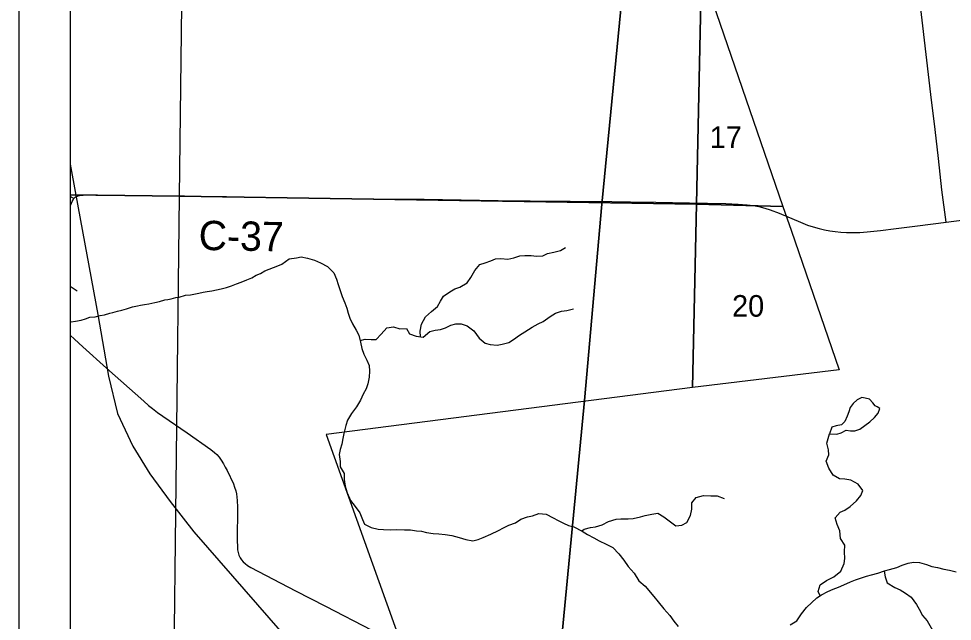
# Model space of a CAD drawing. Extents: x 0 to 34, y -5.4 to 22.
# Drawn here: x 2 to 3.809, y 15.324 to 16.492 of the extents above; entities that cross this region are included whole.
import ezdxf

# ---------------------------------------------------------------- set-up
doc = ezdxf.new("R2010")
doc.units = 0
for name, color, linetype in [('Default', 7, 'Continuous'), ('GM_X_County_Road', 7, 'Continuous'), ('GM_X_County_Road_Text', 7, 'Continuous'), ('GM_X_Minor_Lake', 7, 'Continuous'), ('GM_X_Minor_River', 7, 'Continuous'), ('GM_X_Rail_Line', 7, 'Continuous'), ('GM_X_Section', 7, 'Continuous'), ('GM_X_Section_Text', 7, 'Continuous'), ('GM_X_Township_Road', 7, 'Continuous'), ('SH_Data', 7, 'Continuous')]:
    doc.layers.add(name, color=color, linetype=linetype)

msp = doc.modelspace()

# ---------------------------------------------------------------- linework, layer by layer
at = {"layer": 'Default'}
for points in [[(2.1, 17.1559), (2.1, 16.1508), (2.3117, 16.1481), (2.3239, 17.1531)], [(2.1, 16.1508), (2.1, 15.1447), (2.2999, 15.1427), (2.3117, 16.1481)]]:
    msp.add_lwpolyline(points, close=True, dxfattribs=at)
at = {"layer": 'GM_X_County_Road'}
for points in [[(2.1072, 16.1435), (2.102, 16.1464), (2.1, 16.1475)], [(2.1, 16.1292), (2.1004, 16.13), (2.1023, 16.1343), (2.1039, 16.1377), (2.1054, 16.1407), (2.1072, 16.1435)], [(2.1072, 16.1435), (2.1087, 16.1452), (2.1101, 16.1465), (2.1124, 16.1477), (2.115, 16.1487), (2.1181, 16.1494), (2.1209, 16.1499), (2.1252, 16.1503), (2.1328, 16.1505), (2.1496, 16.1502), (2.1826, 16.1497), (2.275, 16.1487), (2.3214, 16.1484), (2.373, 16.1476), (2.4028, 16.1472), (2.4525, 16.1463), (2.5171, 16.1456), (2.5593, 16.1448), (2.6401, 16.1437), (2.6885, 16.1432), (2.7854, 16.142), (2.9289, 16.1399), (2.991, 16.1392), (3.0687, 16.1385), (3.1495, 16.1376), (3.1624, 16.1373)], [(3.1624, 16.1373), (3.1855, 16.137), (3.2346, 16.1362), (3.2998, 16.1353), (3.37, 16.1336), (3.3942, 16.1326), (3.4115, 16.1313), (3.4231, 16.1298), (3.4341, 16.1278), (3.446, 16.1247), (3.4559, 16.1215), (3.4734, 16.1148), (3.5147, 16.0975), (3.5286, 16.0921), (3.5392, 16.0885), (3.5513, 16.0853), (3.5614, 16.0827), (3.572, 16.0807), (3.5819, 16.0794), (3.5931, 16.0784), (3.6043, 16.0776), (3.6161, 16.0773), (3.6298, 16.0777), (3.6441, 16.0788), (3.6701, 16.0816), (3.7003, 16.0855), (3.7416, 16.0906), (3.7969, 16.0976), (3.9522, 16.1174)], [(2.1, 15.8783), (2.1084, 15.8705), (2.1246, 15.8559), (2.1703, 15.8148), (2.2426, 15.7504), (2.2517, 15.7425), (2.2595, 15.7363), (2.2689, 15.7289), (2.2791, 15.7216), (2.3263, 15.689), (2.3726, 15.6566), (2.3794, 15.6513), (2.3839, 15.6472), (2.3883, 15.6423), (2.3922, 15.6365), (2.3967, 15.6292), (2.4004, 15.6228), (2.4038, 15.6161), (2.416, 15.5903), (2.4184, 15.5838), (2.4206, 15.5766), (2.4219, 15.5709), (2.4228, 15.5644), (2.4234, 15.5581), (2.4239, 15.5451), (2.4235, 15.4789), (2.4237, 15.4692), (2.4242, 15.4624), (2.4251, 15.4573), (2.4268, 15.4519), (2.4293, 15.4468), (2.4319, 15.443), (2.4351, 15.4391), (2.4387, 15.4356), (2.4432, 15.432), (2.4499, 15.4279), (2.5362, 15.383), (2.5943, 15.3533), (2.6843, 15.3064)]]:
    msp.add_lwpolyline(points, dxfattribs=at)
at = {"layer": 'GM_X_Minor_Lake'}
for points in [[(3.6634, 15.7393), (3.6594, 15.7415), (3.6553, 15.7473), (3.6486, 15.7546), (3.6399, 15.7563), (3.6335, 15.7575), (3.6247, 15.7531), (3.6167, 15.746), (3.6112, 15.7385), (3.6085, 15.7302), (3.6053, 15.7215), (3.601, 15.7113), (3.5941, 15.705), (3.5842, 15.7025), (3.5754, 15.7003), (3.5713, 15.6872)], [(3.5713, 15.6872), (3.5851, 15.6865), (3.5934, 15.689), (3.6037, 15.6946), (3.6117, 15.6933), (3.62, 15.6928), (3.6299, 15.6964), (3.6395, 15.7031), (3.6491, 15.7106), (3.6583, 15.7192), (3.6652, 15.7274), (3.6684, 15.7365), (3.6634, 15.7393)]]:
    msp.add_lwpolyline(points, dxfattribs=at)
at = {"layer": 'GM_X_Minor_River'}
for points in [[(2.7783, 15.8754), (2.778, 15.8866), (2.7805, 15.9002), (2.7883, 15.9138), (2.7999, 15.9246), (2.8114, 15.9339), (2.8176, 15.9444), (2.8234, 15.9541), (2.8357, 15.9627), (2.8452, 15.9682), (2.8548, 15.9718), (2.8689, 15.9799), (2.8759, 15.9904), (2.8837, 16.004), (2.8933, 16.0155), (2.9036, 16.0188), (2.9146, 16.0228), (2.9242, 16.0268), (2.9344, 16.027), (2.9476, 16.0256), (2.9594, 16.0288), (2.9708, 16.0324), (2.981, 16.033), (2.9928, 16.0328), (3.0033, 16.0319), (3.0155, 16.0324), (3.025, 16.0368), (3.0372, 16.0397), (3.0501, 16.0425), (3.0596, 16.0484)], [(2.524, 16.0268), (2.5382, 16.0284), (2.5477, 16.0302), (2.5594, 16.0277), (2.5729, 16.0237), (2.585, 16.0185), (2.5985, 16.0119), (2.6108, 15.9995), (2.6158, 15.9869), (2.6191, 15.977), (2.6227, 15.9651), (2.6267, 15.9537), (2.6321, 15.9415), (2.6357, 15.9312), (2.6386, 15.9212), (2.6419, 15.9117), (2.647, 15.9006), (2.654, 15.8884), (2.6591, 15.8788), (2.6623, 15.8651), (2.6647, 15.8525), (2.6691, 15.8414), (2.6746, 15.83), (2.6789, 15.82), (2.6799, 15.8086), (2.6793, 15.7969), (2.6764, 15.7844), (2.6736, 15.7746), (2.6678, 15.7641), (2.6623, 15.7528), (2.6549, 15.7396), (2.6448, 15.7265), (2.6374, 15.7137), (2.6338, 15.7032), (2.6302, 15.6881), (2.6278, 15.6783), (2.6261, 15.6673), (2.6232, 15.6571), (2.6208, 15.6469), (2.6232, 15.6336), (2.6231, 15.6233), (2.6304, 15.6103), (2.631, 15.5985), (2.6327, 15.586), (2.6366, 15.5726), (2.6428, 15.5577), (2.6517, 15.5462), (2.6613, 15.5343), (2.666, 15.5213), (2.67, 15.5118), (2.6832, 15.5058), (2.6967, 15.5022), (2.7069, 15.502), (2.7209, 15.5014), (2.7327, 15.5016), (2.7474, 15.5013), (2.7591, 15.5008), (2.7709, 15.4994), (2.7807, 15.4985), (2.7905, 15.4957), (2.8033, 15.4939), (2.8143, 15.4934), (2.8264, 15.492), (2.8392, 15.4899), (2.8535, 15.4862), (2.8667, 15.4822), (2.8803, 15.4801), (2.8901, 15.4822), (2.9001, 15.4862), (2.9149, 15.4928), (2.9298, 15.5001), (2.9397, 15.5053), (2.9496, 15.51), (2.963, 15.5147), (2.9733, 15.5221), (2.9859, 15.5265), (2.9954, 15.5282), (3.0079, 15.5325), (3.0219, 15.5312), (3.0358, 15.5245), (3.0455, 15.5194), (3.0557, 15.5139), (3.0654, 15.5096), (3.0756, 15.5067), (3.0921, 15.4985), (3.1019, 15.4922), (3.1146, 15.4856), (3.1247, 15.4801), (3.1386, 15.4734), (3.1514, 15.4671), (3.1629, 15.4548), (3.1729, 15.4425), (3.1807, 15.4302), (3.1926, 15.4171), (3.2018, 15.4025), (3.2137, 15.3917), (3.2308, 15.3717), (3.2389, 15.3613), (3.2501, 15.3482), (3.2616, 15.3351), (3.2697, 15.324)], [(2.1, 15.9037), (2.1016, 15.9045), (2.1104, 15.9058), (2.121, 15.9079), (2.1294, 15.9104), (2.1382, 15.9133), (2.1484, 15.9143), (2.1579, 15.9164), (2.1666, 15.9181), (2.1769, 15.921), (2.1826, 15.9228), (2.1918, 15.9249), (2.2001, 15.927), (2.2089, 15.9299), (2.2203, 15.9335), (2.2302, 15.9356), (2.2359, 15.9367), (2.2435, 15.9377), (2.2522, 15.9394), (2.2637, 15.9422), (2.2728, 15.944), (2.283, 15.9468), (2.2888, 15.9479), (2.2952, 15.9493), (2.3047, 15.9514), (2.3112, 15.9524), (2.3234, 15.956), (2.3328, 15.957), (2.3393, 15.958), (2.3488, 15.9601), (2.3576, 15.9618), (2.3655, 15.9632), (2.3746, 15.9646), (2.3834, 15.9667), (2.3925, 15.9684), (2.4028, 15.9709), (2.4123, 15.9742), (2.4222, 15.9778), (2.4314, 15.981), (2.4421, 15.9858), (2.4516, 15.9898), (2.4604, 15.9946), (2.4684, 15.9982), (2.4772, 16.003), (2.4856, 16.0066), (2.494, 16.0095), (2.502, 16.0132), (2.51, 16.0165), (2.524, 16.0268)], [(2.6615, 15.8683), (2.6711, 15.871), (2.6832, 15.8704), (2.693, 15.8702), (2.7026, 15.8803), (2.7131, 15.8927), (2.726, 15.8947), (2.7384, 15.8911), (2.7516, 15.8912), (2.7575, 15.8809), (2.7703, 15.8769), (2.7835, 15.8744), (2.7966, 15.8859), (2.8072, 15.8884), (2.8171, 15.8894), (2.827, 15.8926), (2.8373, 15.8977), (2.8472, 15.9006), (2.8574, 15.9004), (2.869, 15.8968), (2.8821, 15.8867), (2.8921, 15.8729), (2.9037, 15.8628), (2.9135, 15.8604), (2.9271, 15.859), (2.9366, 15.8611), (2.9495, 15.8643), (2.959, 15.8699), (2.9705, 15.8784), (2.9809, 15.8851), (2.995, 15.8939), (3.0069, 15.9005), (3.0164, 15.9053), (3.0298, 15.915), (3.0401, 15.9212), (3.0519, 15.9252), (3.0621, 15.9262), (3.0751, 15.9294)], [(3.5528, 15.3734), (3.5492, 15.3818), (3.5528, 15.3947), (3.5651, 15.4032), (3.5792, 15.4101), (3.593, 15.4209), (3.5993, 15.4356), (3.6006, 15.4458), (3.6004, 15.4587), (3.601, 15.4712), (3.5926, 15.4846), (3.5913, 15.4991), (3.5858, 15.5113), (3.5819, 15.5243), (3.5915, 15.5355), (3.601, 15.5395), (3.611, 15.5462), (3.6237, 15.5573), (3.6318, 15.5674), (3.6357, 15.5776), (3.6268, 15.5899), (3.6126, 15.5977), (3.6005, 15.5994), (3.5907, 15.6), (3.5783, 15.6074), (3.5695, 15.6208), (3.5644, 15.6342), (3.5699, 15.6463), (3.5689, 15.6561), (3.5661, 15.6691), (3.5713, 15.6872)], [(3.0912, 15.4989), (3.0956, 15.5022), (3.1081, 15.5054), (3.1176, 15.5072), (3.1305, 15.5107), (3.1428, 15.5173), (3.1576, 15.522), (3.1671, 15.5226), (3.1807, 15.5224), (3.1906, 15.5234), (3.2046, 15.5262), (3.2141, 15.529), (3.227, 15.5315), (3.2388, 15.5335), (3.25, 15.5261), (3.2605, 15.5187), (3.2732, 15.5087), (3.2853, 15.51), (3.2949, 15.5155), (3.3019, 15.5287), (3.3044, 15.5411), (3.3046, 15.5533), (3.3127, 15.5638), (3.3271, 15.5677), (3.3411, 15.5671), (3.3536, 15.5672), (3.3672, 15.5617)], [(3.4948, 15.3171), (3.5081, 15.3245), (3.5167, 15.338), (3.5267, 15.3503), (3.5463, 15.3694), (3.5559, 15.3753), (3.5681, 15.3815), (3.5784, 15.3863), (3.5883, 15.3899), (3.599, 15.3942), (3.6116, 15.4005), (3.6215, 15.4041), (3.6333, 15.4081), (3.6428, 15.4113), (3.6527, 15.4138), (3.6645, 15.4174), (3.6774, 15.4214), (3.6873, 15.4242), (3.7014, 15.4282), (3.7116, 15.4325), (3.7234, 15.4365), (3.7337, 15.4386), (3.7458, 15.438), (3.759, 15.4336), (3.7695, 15.43), (3.7804, 15.4283), (3.7925, 15.4247), (3.8034, 15.4226), (3.8166, 15.4198)], [(3.6771, 15.4213), (3.6791, 15.4103), (3.6831, 15.3981), (3.698, 15.3891), (3.7082, 15.3848), (3.7183, 15.3782), (3.7292, 15.3708), (3.7395, 15.3566), (3.7447, 15.347), (3.7516, 15.3348), (3.7602, 15.3247), (3.7683, 15.311), (3.773, 15.3014), (3.788, 15.2909), (3.7978, 15.2866), (3.8109, 15.2825)], [(3.2697, 15.324), (3.2779, 15.3136)]]:
    msp.add_lwpolyline(points, dxfattribs=at)
at = {"layer": 'GM_X_Rail_Line'}
msp.add_lwpolyline([(2.1, 20.2033), (2.1, 14.1), (2.9527, 14.1), (2.9641, 14.2324), (3.0059, 14.7462), (3.0382, 15.1455), (3.0967, 15.7517), (3.13, 16.1326), (3.2432, 17.2942), (3.3599, 18.5136), (3.3607, 18.5226), (3.3669, 18.5872), (3.3865, 18.7781), (3.4297, 19.2264), (3.4301, 19.2311), (3.4303, 19.2337), (3.46, 19.8188), (3.4778, 20.1697), (3.2417, 20.1756), (2.1537, 20.2026)], close=True, dxfattribs=at)
for points in [[(3.2432, 17.2942), (3.13, 16.1326), (3.0967, 15.7517), (3.0382, 15.1455), (3.0059, 14.7462), (4.0439, 14.8538), (4.7395, 14.9295)], [(2.1, 16.2102), (2.1109, 16.1503), (2.1533, 15.9186), (2.1742, 15.7991), (2.1915, 15.7268), (2.2211, 15.6634), (2.254, 15.6096), (2.2936, 15.5559), (2.3392, 15.4972), (2.6567, 15.1332), (3.5187, 14.1225), (3.5377, 14.1)]]:
    msp.add_lwpolyline(points, dxfattribs=at)
at = {"layer": 'GM_X_Section'}
for points in [[(2.3239, 17.1531), (3.1329, 17.1374), (3.323, 16.5877), (3.3134, 16.1326), (2.3117, 16.1481)], [(3.3134, 16.1326), (3.323, 16.5877), (3.4807, 16.1279)], [(2.3117, 16.1481), (3.3134, 16.1326), (3.3056, 15.7771), (2.5957, 15.6862), (2.936, 14.7352), (2.2946, 14.6693), (2.2999, 15.1427)], [(3.4807, 16.1279), (3.4966, 16.0822), (3.5898, 15.8116), (3.3056, 15.7771), (3.3134, 16.1326)]]:
    msp.add_lwpolyline(points, close=True, dxfattribs=at)
at = {"layer": 'GM_X_Township_Road'}
msp.add_line((2.1, 15.9733), (2.1132, 15.9646), dxfattribs=at)
msp.add_lwpolyline([(3.7969, 16.0976), (3.7889, 16.1601), (3.7822, 16.2212), (3.7757, 16.2774), (3.7677, 16.3453), (3.7426, 16.5563), (3.7308, 16.655), (3.7149, 16.7914), (3.6867, 17.0315), (3.679, 17.0988), (3.6735, 17.1451), (3.6652, 17.2098), (3.6524, 17.3166), (3.6522, 17.3176)], dxfattribs=at)
at = {"layer": 'SH_Data'}
for p, q in [((2, 21), (2, 14)), ((2.1, 20.9), (2.1, 14.1))]:
    msp.add_line(p, q, dxfattribs=at)

# ---------------------------------------------------------------- texts
at = {"layer": 'GM_X_County_Road_Text'}
msp.add_text('C-37', height=0.05682, rotation=358.9701, dxfattribs=at).set_placement((2.3484, 16.0439))
at = {"layer": 'GM_X_Section_Text'}
for s, p in [('17', (3.3389, 16.2416)), ('20', (3.3823, 15.9144))]:
    msp.add_text(s, height=0.04186, rotation=0, dxfattribs=at).set_placement(p)

doc.saveas('drawing.dxf')
